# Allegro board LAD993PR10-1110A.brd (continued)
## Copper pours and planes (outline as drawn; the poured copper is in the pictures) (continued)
B++ on BOTTOM (solid shape): 50.05,30.2 50.05,29.45 49.92,29.33 49.54,29.33 49.16,28.95 49.16,28.31 48.27,27.42 48.27,24.22 47.76,23.72 47.76,19.68 47.81,19.62 47.81,19.54 48.19,19.17 48.27,19.17 48.6,18.84 49.49,18.84 49.94,18.39 49.94,16.72 50.67,15.99 52.08,15.99 52.59,16.5 53.62,16.5 53.98,16.14 55.74,16.14 56.05,16.45 56.57,16.45 56.65,16.37 56.65,15.87 57.16,15.36 57.16,13.83 57.92,13.07 58.64,13.07 58.7,13.02 58.7,10.67 58.43,10.4 58.43,8.12 58.18,7.86 55.38,7.86 52.59,10.66 49.03,10.66 48.33,11.36 48.33,15.67 46.4,17.6 46.4,18.11 44.46,20.06 44.46,20.76 44.91,20.76 44.91,21.46 44.46,21.46 44.46,21.96 44.91,21.96 44.91,22.66 44.46,22.66 44.46,29.07 45.67,30.28 49.97,30.28
B+_AMP on BOTTOM (solid shape): 267.9,21.39 267.9,21.05 268.03,20.92 269.27,20.92 269.34,20.85 269.34,19.99 269.31,19.95 267.45,19.95 267.05,20.35 267.05,21.38 267.27,21.6 267.7,21.6
B+_AMP on BOTTOM (solid shape): 262.57,31.03 263.23,31.03 263.27,31.07 263.69,31.07 263.87,30.89 263.87,30.39 263.31,29.84 262.81,29.84 262.74,29.77 262.73,29.77 262.65,29.71 262.58,29.62 262.58,29.61 262.25,29.29 258.05,29.29 257.88,29.46 257.88,31.16 258.45,31.74 261.86,31.74
B+_AMP on IN2 (solid shape): outline of 751 points within 258.35,19.95 269.68,31.87
B+_CAM on BOTTOM (solid shape): 211.52,61.14 211.52,58.04 211.21,57.74 210.04,57.74 209.64,58.13 209.22,58.13 208.9,58.45 208.9,60.98 209.28,61.36 211.3,61.36
B+_CAM on BOTTOM (solid shape): 228.51,45.68 228.51,45.39 228.6,45.3 228.87,45.3 228.97,45.2 228.97,44.92 228.89,44.75 228.91,44.57 228.39,44.04 228.39,42.9 228.28,42.78 227.57,42.78 227.47,42.89 227.47,44.11 227.47,44.41 227.47,44.42 227.49,44.54 227.47,44.67 227.47,44.68 227.47,45.04 227.47,45.05 227.49,45.18 227.47,45.3 227.47,45.31 227.47,45.68 227.57,45.79 228.41,45.79
B+_CAM on IN4 (solid shape): 211.54,58 211.54,57.52 211.06,57.04 209.97,57.04 209.84,57.17 209.84,57.83 209.74,57.93 209.74,58.31 209.89,58.46 211.08,58.46
B+_CAM on IN4 (solid shape): 228.6,46.26 229,46.26 229.19,46.07 229.19,45.18 228.84,44.82 228.84,44.72 228.56,44.44 228.03,44.44 227.75,44.72 227.75,46.17 227.85,46.27 228.58,46.27
BATDRV_CHG on TOP (solid shape): 40.01,16.5 40.01,15.87 40.14,15.74 40.52,15.74 40.65,15.61 40.65,15.23 40.52,15.1 39.51,15.1 39.25,15.36 39.25,16.5 39.35,16.6 39.92,16.6
BATDRV_CHG on BOTTOM (solid shape): 34.66,37.58 34.66,37.33 34.55,37.23 31.53,37.23 31.46,37.3 31.46,37.38 31.53,37.46 32.83,37.46 33.06,37.68 34.55,37.68
BATDRV_CHG on IN1 (solid shape): 34.74,37.65 34.74,37.26 34.65,37.17 34.61,37.15 34.57,37.14 33.98,37.14 33.6,36.76 33.6,36.31 32.97,36.31 32.97,37.14 33.6,37.77 34.62,37.77
BATSRC_CHG on TOP (solid shape): 39,16.5 39,15.36 38.74,15.1 37.73,15.1 37.6,15.23 37.6,15.61 37.73,15.74 38.11,15.74 38.24,15.87 38.24,16.5 38.34,16.6 38.9,16.6
BATSRC_CHG on BOTTOM (solid shape): 34.27,38.5 34.27,38.17 34.2,38.09 33.13,38.09 32.67,37.63 31.53,37.63 31.46,37.71 31.46,37.79 31.53,37.86 32.57,37.86 33.28,38.57 34.2,38.57
BATT++ on BOTTOM (solid shape): 47.19,16.52 47.19,11.12 46.05,9.97 46.05,9.17 45.87,8.99 41.79,8.99 41.41,9.38 41.41,13.58 41.6,13.77 43.76,13.77 44.46,14.47 44.46,16.5 44.84,16.88 46.83,16.88
BST1_5V on BOTTOM (solid shape): 52.14,26.34 52.14,25.75 52.11,25.71 51.9,25.71 51.83,25.72 51.75,25.71 50.27,25.71 50.16,25.82 50.16,26.47 50.22,26.53 51.95,26.53
BST1_NVVDD on BOTTOM (solid shape): 173.95,57.65 174.63,56.96 174.79,56.96 174.88,56.87 174.88,56.33 174.91,56.3 174.91,56.05 174.66,56.05 173.06,57.65 173.06,58.28 173.95,58.28
BST1_NVVDDS on TOP (solid shape): 202.8,56.3 202.8,55.15 203.41,54.55 204.01,53.95 204.12,53.84 204.12,53.71 204.07,53.66 203.13,53.66 201.86,54.92 201.86,56.33 201.89,56.35 202.75,56.35
BST2_NVVDD on BOTTOM (solid shape): 174.91,53.79 174.91,53.53 174.89,53.45 174.88,53.38 174.88,52.97 174.86,52.95 174.66,52.95 173.92,52.21 173.92,51.63 173.9,51.6 173.03,51.6 173.03,52.29 173.34,52.59 173.36,52.59 174.61,53.84 174.86,53.84
BST_1VALWP on BOTTOM (solid shape): 249.12,18.68 249.12,18.21 249.69,17.64 249.69,16.78 249.61,16.7 249.49,16.7 249.41,16.78 249.41,17.29 248.49,18.21 248.49,18.67 248.54,18.72 249.08,18.72
BST_1VALWP_R on BOTTOM (solid shape): 249.13,19.62 249.13,19.15 249.09,19.1 248.49,19.1 248.1,18.72 247.72,18.72 247.66,18.79 247.66,19.23 248.1,19.68 249.08,19.68
BST_3V on BOTTOM (solid shape): 51.98,20.39 51.98,19.33 52.03,19.28 52.03,18.03 51.9,17.9 50.99,17.9 50.96,17.92 50.96,18.51 51.77,19.31 51.77,20.4 51.82,20.46 51.92,20.46
BST_+0.95VSP on TOP (solid shape): 69.4,70.68 69.4,70.02 69.35,69.97 68.72,69.97 68.53,69.78 68.53,68.67 68.45,68.59 68.31,68.59 68.25,68.66 68.25,70.07 68.33,70.15 68.39,70.25 68.39,70.26 68.63,70.49 68.64,70.5 68.75,70.56 68.83,70.66 68.9,70.73 69.35,70.73
BST_+0.95VSP_R on TOP (solid shape): 71.18,70.64 71.18,70.05 71.12,69.99 69.85,69.99 69.79,70.05 69.79,70.55 69.97,70.73 71.09,70.73
BST_+1.0VSP on BOTTOM (solid shape): 222.13,46.9 222.13,46.22 222.39,45.96 222.39,44.83 222.31,44.76 222.21,44.76 221.69,45.27 221.69,45.9 221.37,46.22 221.37,46.9 221.44,46.96 222.07,46.96
BST_+1.0VSP_R on BOTTOM (solid shape): 222.07,47.81 222.07,47.33 222.03,47.29 221.45,47.29 221.4,47.35 221.4,47.55 221.26,47.68 220.67,47.68 220.62,47.74 220.62,48.09 220.67,48.14 221.74,48.14
BST_+1.8VSP on BOTTOM (solid shape): 206.25,121.54 206.25,119.57 206.18,119.5 206.05,119.5 205.99,119.56 205.99,120.22 205.61,120.6 205.61,121.53 205.66,121.58 206.2,121.58
BST_+1.8VSP_R on BOTTOM (solid shape): 206.23,121.94 205.62,121.94 205.37,121.68 205.37,121.55 205.04,121.55 205.01,121.58 205.01,122.33 205.18,122.49 206.23,122.49
BST_+1.35VS_VGAP on BOTTOM (solid shape): 143.55,116.14 143.55,115.46 142.17,114.09 141.74,114.09 141.67,114.16 141.67,114.85 141.74,114.93 142,114.93 142.55,115.48 142.55,116.09 142.66,116.2 143.49,116.2
BTST_CHG on BOTTOM (solid shape): 29.98,35.68 29.98,33.62 30.31,33.29 30.31,32.63 30.29,32.6 29.42,32.6 29.4,32.63 29.4,33.26 29.47,33.34 29.5,33.34 29.7,33.54 29.7,33.57 29.75,33.62 29.75,35.68 29.82,35.74 29.92,35.74
CHG_B+ on TOP (solid shape): 19.31,27.68 19.31,25.14 20.02,24.43 20.02,23.92 19.46,23.92 19.46,23.38 19.49,23.36 19.99,23.36 20.02,23.33 20.02,23.1 19.46,23.1 19.46,22.57 19.49,22.55 19.99,22.55 20.02,22.52 20.02,22.19 19.95,22.12 19.95,18.79 19.41,18.25 17.44,18.25 17.15,18.53 17.15,24.16 17.34,24.35 17.34,26.36 17.34,26.36 17.34,26.72 17.43,26.81 17.72,26.99 17.73,27.32 17.73,27.65 17.74,27.68 17.75,27.72 17.84,27.8 19.19,27.8
CHG_B+ on BOTTOM (solid shape): 19.31,26.53 19.31,24.12 20.46,22.98 23.5,22.98 23.76,22.72 23.76,18.66 23.5,18.41 18.55,18.41 17.28,19.68 17.28,25.52 18.42,26.66 19.19,26.66
CMSRC_CHG on BOTTOM (solid shape): 25.91,37.55 25.96,37.55 26.38,37.12 26.98,37.12 27.06,37.05 28.23,37.05 28.28,37 28.28,36.87 28.23,36.82 27.09,36.82 26.88,36.61 25.31,36.61 25.27,36.65 25.27,37.47 25.36,37.56 25.91,37.56
DH1_NVVDD on BOTTOM (solid shape): 169.78,56.15 169.78,55.51 169.4,55.13 168.26,55.13 168.11,55.29 168.11,55.79 168.67,56.35 169.58,56.35
DH1_NVVDD on BOTTOM (solid shape): 155.31,51.55 155.31,50.74 155.19,50.62 154.06,50.62 153.95,50.74 153.95,51.49 154.43,51.97 154.89,51.97
DH1_NVVDD on IN4 (solid shape): 169.78,56.17 169.78,55.9 169.02,55.13 168.26,55.13 168.11,55.29 168.11,55.79 168.67,56.35 169.61,56.35
DH1_NVVDD on IN4 (solid shape): 155.28,51.58 155.28,50.74 155.17,50.62 154.02,50.62 153.93,50.71 153.93,51.48 154.42,51.96 154.9,51.96
DH1_NVVDD on IN4 (solid shape): 175.19,57.57 175.19,57.22 174.84,56.86 173.64,56.86 173.59,56.91 173.59,57.37 173.72,57.5 173.92,57.5 174.43,58 174.76,58
DH1_NVVDDS on TOP (solid shape): 203.01,53.48 204.07,53.48 204.12,53.43 204.12,53.3 204.07,53.25 202.32,53.25 201.84,53.73 201.84,54.12 201.94,54.22 202.27,54.22
DH1_NVVDDS on BOTTOM (solid shape): 206.28,63.11 206.28,62.4 206.05,62.17 205.19,62.17 205.06,62.3 205.06,63.2 205.44,63.58 205.81,63.58
DH1_NVVDDS on BOTTOM (solid shape): 200.84,63.9 200.84,62.96 200.69,62.8 199.5,62.8 199.29,63.01 199.29,63.36 199.47,63.54 199.7,63.54 200.16,64 200.74,64
DH1_NVVDDS on IN4 (solid shape): 202.91,53.56 202.91,53.15 202.78,53.03 202.37,53.03 201.34,54.05 201.34,54.4 201.51,54.57 201.9,54.57
DH1_NVVDDS on IN4 (solid shape): 206.28,62.53 206.28,62.39 205.98,62.09 204.86,62.09 204.76,62.19 204.76,62.68 204.84,62.75 205.19,62.75 205.19,62.76 206.05,62.76
DH1_NVVDDS on IN4 (solid shape): 200.75,63.72 200.75,62.23 200.39,61.86 200.11,61.86 200.09,61.89 199.95,61.89 199.82,62.01 199.82,63.78 199.96,63.92 200.54,63.92
DH2_NVVDD on BOTTOM (solid shape): 152.04,56.21 152.04,55.6 151.95,55.51 150.12,55.51 149.95,55.69 149.95,56.08 150.2,56.33 151.92,56.33
DH2_NVVDD on BOTTOM (solid shape): 150.99,50.99 150.99,50.26 150.72,49.99 150.72,49.55 150.56,49.39 150.09,49.39 149.85,49.63 149.85,50.05 149.67,50.23 149.67,51.02 149.77,51.12 150.86,51.12
DH2_NVVDD on BOTTOM (solid shape): 175.35,53.76 175.35,52.51 175.2,52.36 175.2,52.34 174.99,52.14 174.99,51.86 174.66,51.53 174.43,51.53 174.3,51.65 174.3,52.19 174.69,52.57 174.91,52.57 175.12,52.77 175.12,53.76 175.18,53.83 175.28,53.83
DH2_NVVDD on IN1 (solid shape): 151.24,51.02 151.24,50.71 151.01,50.49 149.72,50.49 149.52,50.69 149.52,51.1 149.62,51.21 151.06,51.21
DH2_NVVDD on IN1 (solid shape): 175.27,52.64 175.27,52.42 174.99,52.14 174.99,51.65 174.71,51.37 174.33,51.37 174.24,51.46 174.24,51.82 174.3,51.88 174.3,52.19 174.89,52.77 175.14,52.77
DH_CHG on BOTTOM (solid shape): 25.98,19.02 25.98,17.96 25.79,17.77 24.77,17.77 24.48,18.07 24.48,19.03 24.68,19.23 25.77,19.23
DH_CHG on BOTTOM (solid shape): 29.58,35.7 29.58,33.59 29.45,33.47 29.25,33.47 29.12,33.59 29.12,34.38 29.37,34.64 29.37,35.7 29.41,35.74 29.54,35.74
DH_CHG on IN1 (solid shape): 29.66,34.47 29.66,32.18 29.03,32.18 29.03,34.47 29.16,34.6 29.54,34.6
DL1_NVVDD on BOTTOM (solid shape): 163.27,56.36 163.27,55.43 162.95,55.11 162.57,55.11 162.19,55.49 162.19,56.38 162.32,56.51 163.13,56.51
DL1_NVVDD on BOTTOM (solid shape): 160.79,51.81 160.79,50.85 160.63,50.69 159.67,50.69 159.57,50.79 159.57,51.19 159.85,51.47 159.85,51.78 160.07,52 160.6,52
DL1_NVVDD on BOTTOM (solid shape): 173.4,55.84 173.4,55.73 173.69,55.44 174.46,55.44 174.53,55.36 174.53,55.26 174.51,55.24 173.47,55.24 173.14,55.57 172.76,55.57 172.32,56 172.32,56.28 172.53,56.48 172.76,56.48
DL1_NVVDD on IN1 (solid shape): 163.41,56.35 163.41,55.84 163.18,55.62 162.34,55.62 162.11,55.84 162.11,56.25 162.29,56.43 163.33,56.43
DL1_NVVDD on IN1 (solid shape): 173.42,55.92 173.42,55.54 173.23,55.35 172.86,55.35 171.96,56.25 171.96,56.5 172.24,56.78 172.56,56.78
DL1_NVVDDS on TOP (solid shape): 204.89,56.17 204.89,54.09 204.86,54.07 204.73,54.07 204.68,54.12 204.68,54.92 204.35,55.26 204.35,56.15 204.5,56.3 204.75,56.3
DL1_NVVDDS on BOTTOM (solid shape): 200.64,69.48 200.64,68.67 200.47,68.5 199.5,68.5 199.31,68.69 199.31,69.48 199.54,69.71 200.42,69.71
DL1_NVVDDS on BOTTOM (solid shape): 206.08,69.71 206.08,68.77 205.88,68.57 205.09,68.57 204.86,68.8 204.86,69.74 205.01,69.89 205.9,69.89
DL1_NVVDDS on IN1 (solid shape): 204.96,56.84 204.96,55.26 204.84,55.13 204.51,55.13 204.33,55.31 204.33,56.81 204.38,56.86 204.94,56.86
DL1_NVVDDS on IN1 (solid shape): 206,69.69 206,68.6 205.85,68.44 204.9,68.44 204.82,68.52 204.82,69.75 204.96,69.89 205.8,69.89
DL1_NVVDDS on IN1 (solid shape): 201.1,69.08 201.71,69.08 201.79,69 201.79,68.49 201.74,68.44 200.34,68.44 200.06,68.72 200.06,69.46 200.21,69.61 200.57,69.61
DL2_NVVDD on BOTTOM (solid shape): 173.29,54.19 173.29,53.94 172.6,53.25 172.35,53.25 172.2,53.41 172.2,53.71 172.83,54.35 173.14,54.35
DL2_NVVDD on BOTTOM (solid shape): 145.12,57.01 145.12,56.23 144.94,56.05 144.94,55.68 144.77,55.51 144.49,55.51 143.98,56.02 143.98,56.79 144.36,57.17 144.97,57.17
DL2_NVVDD on BOTTOM (solid shape): 145.22,51.45 145.22,51.15 145.05,50.97 145.05,49.62 144.85,49.42 144.47,49.42 144.31,49.58 144.31,50.23 144.08,50.46 144.08,50.84 144.82,51.58 145.09,51.58
DL2_NVVDD on IN3 (solid shape): 173.29,54.24 173.29,54.02 172.5,53.23 172.25,53.23 172.12,53.36 172.12,53.79 172.68,54.35 173.19,54.35
DL2_NVVDD on IN3 (solid shape): 144.99,52.04 145.49,51.54 145.49,50.62 145.41,50.55 144.54,50.55 144.41,50.68 144.41,52.02 144.54,52.15 144.99,52.15
DL2_NVVDD on IN3 (solid shape): 145.12,57.06 145.12,55.59 144.99,55.46 144.92,55.46 144.87,55.51 144.56,55.51 144.03,56.05 144.03,56.84 144.36,57.17 145.02,57.17
DL_CHG on BOTTOM (solid shape): 30.77,35.68 30.77,34.84 31.48,34.13 31.48,33.8 31.35,33.67 31.15,33.67 30.57,34.25 30.57,35.68 30.63,35.74 30.71,35.74
DL_CHG on BOTTOM (solid shape): 23,27.68 23,27.42 22.87,27.3 22.87,26.79 22.74,26.66 22.41,26.66 21.8,27.27 21.8,27.69 21.91,27.8 22.87,27.8
DL_CHG on IN4 (solid shape): 31.58,34.15 31.58,33.52 30.74,32.68 30.36,32.68 30.36,33.21 30.92,33.77 30.92,33.9 30.54,34.28 30.54,34.53 30.74,34.74 31,34.74
EDPVDD on TOP (solid shape): 66.9,41.93 67.14,41.93 68.82,40.25 68.82,39.36 68.59,39.13 67.34,39.13 67.21,39.26 67.21,39.81 66.13,40.88 65.29,40.88 65.28,40.9 65.28,41.17 65.81,41.17 65.81,41.61 65.28,41.61 65.28,41.92 65.39,42.03 66.8,42.03
GVDD on BOTTOM (solid shape): 261.22,23.23 261.22,22.95 261.58,22.6 262.09,22.6 262.3,22.39 262.3,22.08 262.21,21.99 261.3,21.99 260.69,22.6 260.69,23.28 260.72,23.31 261.15,23.31
IFP_IOVDDA on TOP (solid shape): 160.16,83.2 160.16,82.63 160.22,82.57 160.22,82.11 159.97,81.85 159.13,81.85 159.03,81.96 159.03,83.28 159.15,83.4 159.95,83.4
IFP_IOVDDB on TOP (solid shape): 163.02,84.63 163.02,83.82 163.48,83.35 163.64,83.35 163.77,83.23 163.77,83.01 163.68,82.91 163.15,82.91 162.98,82.74 162.44,82.74 162.39,82.79 162.39,84.57 162.47,84.65 162.47,84.65 162.51,84.68 162.97,84.68
LDO_1VALWP on BOTTOM (solid shape): 249.36,15.2 249.36,14.65 249.26,14.54 249.26,13.96 248.29,12.99 248.29,12.56 248.22,12.49 247.63,12.49 247.53,12.59 247.53,13.33 248.45,14.24 248.45,15.21 248.52,15.29 249.28,15.29
LDO_+0.95VSP on TOP (solid shape): 70.88,67.05 70.88,66.54 70.8,66.46 68.67,66.46 68.59,66.54 68.59,67.1 68.67,67.17 70.75,67.17
LDO_+1.0VSP on BOTTOM (solid shape): 222.05,43.25 222.05,42.71 221.94,42.6 221.34,42.6 221.14,42.4 221.14,41.92 221,41.78 220.73,41.78 220.32,42.2 220.32,42.22 220.02,42.52 220.02,42.52 220.02,43.2 220.14,43.33 221.98,43.33
LDO_+1.8VSP on BOTTOM (solid shape): 205.93,118.02 205.93,117.44 205.11,116.63 203.69,116.63 203.59,116.73 203.59,117.19 203.74,117.34 204.43,117.34 204.66,117.57 204.66,117.8 204.91,118.05 205.62,118.05 205.67,118.1 205.85,118.1
LG_3V on BOTTOM (solid shape): 51.17,20.8 51.17,20.51 50.35,19.7 50.35,19.65 50.12,19.42 49.92,19.42 49.79,19.55 49.79,20.39 50.22,20.81 50.37,20.81 50.43,20.87 51.1,20.87
LG_3V on BOTTOM (solid shape): 61.73,10.72 61.73,10.02 61.07,9.36 61.07,8.98 60.97,8.88 59.32,8.88 59.06,9.13 59.06,9.52 59.19,9.64 60.46,9.64 60.84,10.02 60.84,10.79 60.97,10.91 61.54,10.91
LG_5V on TOP (solid shape): 50.3,37.07 50.3,35.3 50.17,35.17 49.54,35.17 49.41,35.3 49.41,37.07 49.54,37.2 50.17,37.2
LG_5V on TOP (solid shape): 50.21,23.18 50.21,22.59 50.09,22.47 49.19,22.47 49.06,22.6 49.06,23.38 49.16,23.49 49.91,23.49
LG_5V on BOTTOM (solid shape): 50.1,36.92 50.1,36.75 50.3,36.56 50.3,34.02 50.17,33.9 49.71,33.9 49.54,34.06 49.54,35.24 49.54,35.24 49.54,37 49.67,37.14 49.89,37.14
LG_5V on BOTTOM (solid shape): 50.66,22.47 51.11,22.47 51.18,22.4 51.18,22.31 51.12,22.25 50.93,22.25 50.87,22.31 50.05,22.31 49.95,22.41 49.26,22.41 49.12,22.55 49.12,22.84 49.25,22.98 50.15,22.98
LG_+1.35VS_VGAP on BOTTOM (solid shape): 139.94,114.82 139.94,114.16 139.86,114.09 139.02,114.09 138.95,114.16 138.95,114.93 139.13,115.1 139.66,115.1
LG_+1.35VS_VGAP on BOTTOM (solid shape): 144.28,130.9 144.28,129.89 143.57,129.18 143.11,129.18 142.96,129.32 142.96,130.01 143.93,130.98 144.21,130.98
LG_+1.35VS_VGAP on IN1 (solid shape): 139.91,115.38 139.91,114.24 139.74,114.06 139,114.06 138.9,114.16 138.9,115.33 139.15,115.59 139.71,115.59
LG_+1.35VS_VGAP on IN1 (solid shape): 144.28,130.9 144.28,129.89 143.47,129.07 143.06,129.07 142.96,129.17 142.96,130.01 143.93,130.98 144.21,130.98
LINE1-L_C on TOP (solid shape): 296.73,14.41 296.73,13.81 296.7,13.78 295.02,13.78 294.93,13.86 294.93,14.42 295.04,14.53 296.61,14.53
LINE1-L_R on TOP (solid shape): 293.51,14.6 294.52,14.6 294.65,14.47 294.65,13.89 294.57,13.81 292.56,13.81 292.24,14.13 292.24,14.67 292.31,14.75 293.35,14.75
LINE1_R on TOP (solid shape): 294.61,16.27 294.61,15.28 294.56,15.23 293.76,15.23 293.7,15.28 293.7,16.41 293.81,16.52 294.36,16.52
LX1_NVVDD on TOP (solid shape): 167.01,61.66 167.01,52.44 166.13,51.55 163.6,51.55 163.46,51.69 163.46,56.12 164.35,57.01 164.35,58.16 163.59,58.92 160.77,58.92 160.59,58.74 160.59,58.58 160.02,58.58 159.93,58.59 159.8,58.58 159.69,58.49 159.61,58.39 159.6,58.26 159.61,58.13 159.69,58.02 159.8,57.94 159.93,57.93 160.02,57.94 160.59,57.94 160.59,57.65 159.52,56.58 159.52,51.68 159.39,51.55 156.35,51.55 155.84,52.06 155.84,56.12 156.96,57.25 156.96,59.29 157.62,59.95 157.62,61.51 158.4,62.3 166.38,62.3
LX1_NVVDD on BOTTOM (solid shape): 172.68,57.62 174.46,55.84 174.47,55.84 174.53,55.78 174.53,55.69 174.47,55.63 173.7,55.63 173.64,55.68 173.64,56.02 172.35,57.32 171.79,57.32 171.79,58.28 172.68,58.28
LX1_NVVDD on BOTTOM (solid shape): 168.26,62.71 168.26,57.5 166.9,56.14 166.39,56.14 166.15,55.9 166.15,51.7 166.18,51.68 166.05,51.55 163.56,51.55 163.46,51.65 163.46,56.46 163.21,56.71 160.03,56.71 159.64,56.32 159.64,51.56 159.61,51.53 156.97,51.53 156.92,51.58 156.92,57 158.4,58.49 158.4,62.4 159.15,63.14 167.83,63.14
LX1_NVVDDS on TOP (solid shape): 192.16,70.48 192.16,68.82 192.8,68.19 205.62,68.19 205.67,68.14 205.67,65.34 205.47,65.14 195.56,65.14 193.56,63.13 189.85,63.13 189.37,63.62 189.37,70.6 189.62,70.86 191.78,70.86
LX1_NVVDDS on TOP (solid shape): 204.19,56.23 204.19,55.24 204.2,55.21 204.51,54.9 204.51,54.12 204.45,54.07 204.33,54.07 204.25,54.14 204.25,54.17 203.13,55.29 203.13,56.33 203.15,56.35 204.07,56.35
LX1_NVVDDS on BOTTOM (solid shape): 194.45,70.35 194.45,68.7 194.94,68.2 205.66,68.2 205.75,68.11 205.75,65.39 205.51,65.14 195.08,65.14 193.18,63.24 190.27,63.24 189.41,64.1 189.41,71.15 189.87,71.62 193.18,71.62
LX1_NVVDDS on IN1 (solid shape): 204.12,55.03 204.12,54.78 204.02,54.68 203.59,54.68 202.45,55.82 202.45,56.05 202.55,56.15 203.01,56.15
LX1_NVVDDS on IN3 (solid shape): 194.45,70.98 194.45,68.7 194.95,68.19 205.57,68.19 205.67,68.09 205.67,65.31 205.5,65.14 195.08,65.14 193.32,63.38 193.27,63.38 192.87,62.98 190.71,62.98 189.37,64.33 189.37,70.7 189.9,71.24 194.19,71.24
LX1_NVVDDS on IN4 (solid shape): 194.45,70.98 194.45,68.7 194.95,68.19 205.57,68.19 205.75,68.01 205.75,65.45 205.5,65.19 195.06,65.19 192.85,62.98 190.03,62.98 189.39,63.62 189.39,70.73 189.9,71.24 194.19,71.24
LX2_NVVDD on TOP (solid shape): 157.21,61.86 157.21,60.11 156.7,59.6 155.41,59.6 155.25,59.45 155.25,57.19 149.31,57.19 148.27,56.15 148.27,46.35 148.14,46.22 145.53,46.22 145.35,46.4 145.35,59.52 145.55,59.72 145.55,61.41 146.52,62.37 156.7,62.37
LX2_NVVDD on BOTTOM (solid shape): 174.51,54.19 174.51,54.04 174.48,54.01 174.35,54.01 172.65,52.31 172.68,52.29 172.68,51.65 172.65,51.63 171.82,51.63 171.79,51.65 171.79,52.29 171.94,52.29 173.57,53.91 173.57,54.09 173.65,54.17 174.24,54.17 174.29,54.23 174.47,54.23
LX2_NVVDD on BOTTOM (solid shape): 157.2,62.83 157.21,62.83 157.21,60.11 156.7,59.6 155.41,59.6 155.25,59.45 155.25,57.72 154.72,57.19 149.31,57.19 148.27,56.15 148.27,46.08 148.04,45.85 145.37,45.85 145.35,45.87 145.35,62.16 146.4,63.22 156.81,63.22
LX2_NVVDD on IN1 (solid shape): 157.21,62.84 157.21,60.11 156.7,59.6 155.41,59.6 155.25,59.45 155.25,57.44 155,57.19 149.31,57.19 148.27,56.15 148.27,46.35 148.14,46.22 145.45,46.22 145.35,46.32 145.35,62.2 146.36,63.21 156.85,63.21
LX2_NVVDD on IN3 (solid shape): 173.62,53.53 173.62,52.87 173.29,52.54 173.29,52.14 172.96,51.81 172.65,51.81 172.65,53.03 173.24,53.61 173.54,53.61
LX2_NVVDD on IN3 (solid shape): 148.85,49.83 148.85,49.39 148.82,49.36 148.36,49.36 148.24,49.24 148.24,46.37 148.07,46.19 145.51,46.19 145.35,46.35 145.35,50.35 148.34,50.35
LX2_NVVDD on IN3 (solid shape): 150.31,61.64 150.31,58.17 149.39,57.24 149.36,57.24 148.24,56.12 148.27,56.1 148.27,52.24 148.04,52.01 145.48,52.01 145.35,52.14 145.35,60.19 147.19,62.02 149.92,62.02
LX2_NVVDD on IN4 (solid shape): 157.21,62.7 157.21,60.11 156.7,59.6 155.43,59.6 155.28,59.45 155.28,57.32 155.15,57.19 149.29,57.19 148.27,56.17 148.27,48.59 146.15,46.47 145.35,46.47 145.35,62.67 145.85,63.17 156.74,63.17
LX_1VALWP on TOP (solid shape): 253.25,17.47 253.25,17.34 252.46,16.55 252.46,14.49 252.61,14.34 252.61,12.82 252.36,12.56 251.47,12.56 251.09,12.94 251.09,16.25 250.71,16.63 247.91,16.63 247.79,16.75 247.79,17.64 248.12,17.97 252.74,17.97
LX_1VALWP on BOTTOM (solid shape): 253.26,17.5 253.26,17.15 252.49,16.38 251.61,16.38 251.55,16.45 251.55,16.55 251.88,16.88 251.98,16.88 252.61,17.52 252.62,17.52 252.73,17.63 253.14,17.63
LX_1VALWP on BOTTOM (solid shape): 247.53,18.6 248.1,18.6 248.17,18.53 248.17,18.02 249.18,17.01 249.18,16.73 249.36,16.55 249.36,16.02 249.29,15.94 248.37,15.94 248.12,15.69 248.12,14.42 247.28,13.58 247.28,11.93 247.14,11.79 243.68,11.79 243.44,12.03 243.44,17.47 243.46,17.48 243.46,17.81 244.31,18.66 247.47,18.66
LX_3V on BOTTOM (solid shape): 70.62,14.47 70.62,10.28 70.37,10.02 65.49,10.02 64.14,11.37 59.4,11.37 59.26,11.51 59.26,13.77 60.33,14.85 70.24,14.85
LX_3V on BOTTOM (solid shape): 52.39,20.4 52.39,19.21 53.55,18.04 53.55,16.68 53.5,16.63 53.2,16.63 53.1,16.73 53.1,17.67 52.9,17.87 52.3,17.87 52.17,18 52.17,20.39 52.24,20.46 52.33,20.46
LX_3V on IN1 (solid shape): 53.73,17.71 53.73,16.69 54.38,16.05 54.38,15.72 53.82,15.72 53.1,16.44 53.1,17.71 53.22,17.83 53.6,17.83
LX_5V on TOP (solid shape): 47.59,32.93 47.59,31.19 47.13,30.72 45.48,30.72 45.35,30.85 45.35,31.99 46.36,33.01 47.51,33.01
LX_5V on BOTTOM (solid shape): 50.05,33.52 50.05,30.85 49.92,30.72 45.35,30.72 43.19,28.57 40.14,28.57 39.89,28.82 39.89,32.76 40.78,33.65 49.92,33.65
LX_5V on BOTTOM (solid shape): 52.21,25.26 52.21,24.5 52.46,24.25 52.46,23.62 52.38,23.54 52.38,22.7 52.33,22.65 52.22,22.65 52.16,22.71 52.16,23.88 51.44,24.6 51.44,25.26 51.57,25.39 52.08,25.39
LX_5V on IN4 (solid shape): 52.16,24.58 52.39,24.34 52.4,24.33 52.47,24.2 52.58,24.12 52.61,24.1 52.61,23.87 52.41,23.66 52.13,23.66 51.5,24.3 51.5,25.57 52.16,25.57
LX_+0.95VSP on TOP (solid shape): 71.64,69.21 71.64,68.44 71.38,68.19 71.26,68.19 71.16,68.09 70.36,68.09 70.36,68.09 70.21,68.09 69.93,67.81 68.67,67.81 68.59,67.89 68.59,68.44 68.82,68.67 68.82,69.69 68.97,69.84 71,69.84
LX_+0.95VSP on BOTTOM (solid shape): 72.02,73.14 72.02,68.7 71.13,67.81 68.34,67.81 67.95,68.19 66.05,68.19 65.8,68.44 65.8,69.21 66.56,69.97 68.03,69.97 69.99,71.93 69.99,73.14 70.11,73.27 71.89,73.27
LX_+1.0VSP on TOP (solid shape): 225.31,45.71 225.31,44.87 225.09,44.66 221.17,44.66 220.99,44.83 220.99,45.75 221.13,45.9 221.37,45.9 221.65,45.62 222.18,45.62 222.48,45.92 225.1,45.92
LX_+1.0VSP on BOTTOM (solid shape): 225.43,45.89 225.43,44.77 225.1,44.44 224.34,44.44 224.27,44.52 224.27,44.59 224.34,44.67 224.62,44.67 224.75,44.8 224.75,45.89 224.88,46.01 225.31,46.01
LX_+1.0VSP on BOTTOM (solid shape): 220.55,47.5 220.7,47.43 220.86,47.4 221.12,47.4 221.12,46.22 221.5,45.84 221.5,45.16 222.06,44.6 222.06,44.05 221.98,43.98 217.01,43.98 216.8,44.19 216.8,47.36 216.95,47.51 220.54,47.51
LX_+1.8VSP on TOP (solid shape): 205.58,120.28 206.11,120.28 206.47,120.64 208.85,120.64 209.03,120.46 209.03,119.57 208.85,119.4 205.1,119.4 204.84,119.66 204.84,120.51 204.96,120.64 205.22,120.64
LX_+1.8VSP on BOTTOM (solid shape): 209.05,119.19 209.03,119.17 208.16,119.17 208.11,119.22 208.11,119.34 208.14,119.37 208.16,119.37 208.29,119.5 208.29,120.34 208.47,120.51 209.05,120.51
LX_+1.8VSP on BOTTOM (solid shape): 204.58,122.6 204.58,121.4 204.59,121.38 205.37,121.38 205.37,120.56 205.84,120.09 205.84,119.45 205.9,119.39 205.9,118.79 205.85,118.74 205.64,118.74 205.62,118.76 204.81,118.76 204.2,119.37 201.91,119.37 201.86,119.42 201.86,123.28 201.94,123.36 203.82,123.36
LX_CHG on TOP (solid shape): 25.79,23.99 25.79,22.6 25.66,22.47 24.14,22.47 24.01,22.6 24.01,23.99 24.27,24.25 25.54,24.25
LX_CHG on BOTTOM (solid shape): 31.12,24.76 31.12,19.17 30.74,18.79 26.93,18.79 25.92,19.8 24.39,19.8 24.14,20.06 24.14,22.85 23.27,23.72 23.27,27.27 23.55,27.55 28.33,27.55
LX_CHG on BOTTOM (solid shape): 29.17,35.7 29.17,34.66 28.99,34.48 28.99,32.68 28.94,32.63 28.23,32.63 28.15,32.71 28.15,34.23 28.56,34.64 28.76,34.64 28.97,34.84 28.97,35.7 29,35.74 29.13,35.74
LX_CHG on IN1 (solid shape): 28.78,34.47 28.78,32.69 28.39,32.31 28.08,32.31 28.08,32.88 28.14,32.95 28.14,34.47 28.27,34.6 28.65,34.6
LX_DDR on BOTTOM (solid shape): 106.59,12.36 106.59,9.41 107.2,8.8 107.2,7.33 106.97,7.1 105.5,7.1 105.04,7.56 105.04,8.6 104.96,8.68 104.96,8.74 103.32,10.37 103.32,10.49 103.16,10.66 102.42,10.66 101.31,10.66 101.1,10.86 101.1,12.33 103.03,12.33 103.49,12.79 106.16,12.79
PQ703_S on TOP (solid shape): 38.49,20.44 38.49,19.29 39,18.79 39,17.01 38.87,16.88 34.93,16.88 34.68,17.14 34.68,20.31 34.93,20.56 38.36,20.56
PQ703_S on BOTTOM (solid shape): 42.81,22.98 42.81,19.93 42.68,19.8 42.08,19.8 41.98,19.9 41.98,20.4 41.96,20.43 41.6,20.76 41.25,20.43 41.22,20.4 41.22,19.8 40.52,19.8 39.25,18.53 38.24,18.53 37.73,18.02 37.73,17.26 37.47,17.01 34.81,17.01 34.68,17.14 34.68,22.98 35.06,23.36 42.43,23.36
REGN_CHG on BOTTOM (solid shape): 30.38,35.68 30.38,34.22 31.3,33.29 31.56,33.29 31.58,33.26 31.58,32.63 31.56,32.6 31.35,32.6 30.74,31.99 30.36,31.99 30.24,32.12 30.24,32.38 30.36,32.5 30.52,32.5 30.62,32.6 30.62,33.31 30.16,33.77 30.16,35.68 30.22,35.74 30.31,35.74
RING2 on BOTTOM (solid shape): 291.47,19.93 291.47,19.25 291.73,18.99 291.73,17.9 291.36,17.9 291.36,18.21 291.35,18.23 291.05,18.53 290.74,18.53 290.73,18.55 289.87,18.55 289.57,18.85 289.57,20.31 289.7,20.44 290.97,20.44
RING2 on IN1 (solid shape): 281.34,19.1 281.34,18.33 281.16,18.15 280.63,18.15 279.74,19.04 279.74,19.88 279.89,20.03 280.41,20.03
RING2 on IN1 (solid shape): 290.59,19.47 290.59,19.12 289.62,18.15 288.78,18.15 288.15,18.79 288.15,19.68 290.38,19.68
RING2_R on BOTTOM (solid shape): 295.46,20.36 295.46,19.32 294.43,18.28 294.43,18.03 294.3,17.9 292.11,17.9 292.11,18.48 292.29,18.66 292.87,18.66 293.84,19.62 293.84,20.44 294.12,20.72 295.11,20.72
SLEEVE on BOTTOM (solid shape): 298.33,14.34 298.33,12.71 298.29,12.67 297.61,12.67 297.57,12.72 297.57,14.34 297.7,14.47 298.21,14.47
SLEEVE on BOTTOM (solid shape): 286.9,21.45 286.9,19.68 286.42,19.19 282.55,19.19 282.27,18.91 281.06,18.91 280.93,19.04 280.93,19.93 281.19,20.18 283.22,20.18 284.9,21.86 286.5,21.86
SLEEVE on IN4 (solid shape): 298.34,14.97 298.34,13.41 298.2,13.27 297.17,13.27 297.03,13.41 297.03,15.06 297.11,15.14 298.17,15.14
SLEEVE on IN4 (solid shape): 287.59,22.47 287.59,21.96 287.33,21.71 287.33,21 287.11,20.77 286.53,20.77 286.44,20.86 286.15,20.86 286.06,20.95 286.06,22.06 286.7,22.7 287.36,22.7
SLEEVE_R on BOTTOM (solid shape): 297.26,13.18 297.26,10.28 299.42,8.12 299.42,7.74 299.03,7.36 298.7,7.36 297.93,8.12 297.77,8.12 296.54,9.35 296.54,9.51 296.17,9.87 296.17,13.02 296.37,13.21 297.23,13.21
SNUB_1VALWP on TOP (solid shape): 255.15,11.47 255.08,11.39 254.3,11.39 254.18,11.52 254.18,14.38 254.21,14.42 255.15,14.42
SNUB_3V on BOTTOM (solid shape): 66.3,9.39 66.3,7.1 66.18,6.98 65.54,6.98 65.29,7.23 65.29,8.12 65.03,8.37 64.53,8.37 64.4,8.5 64.4,9.39 64.53,9.52 66.18,9.52
SNUB_5V on TOP (solid shape): 45.22,34.28 45.22,32.88 44.84,32.5 44.84,31.23 44.76,31.15 43.65,31.15 43.57,31.23 43.57,33.52 44.42,34.37 45.14,34.37
SNUB_+0.95VSP on BOTTOM (solid shape): 64.86,69.94 64.86,68.29 64.81,68.24 62.37,68.24 62.09,68.52 62.09,69.57 62.27,69.75 63.04,69.75 63.34,70.05 64.74,70.05
SNUB_+1.8VSP on TOP (solid shape): 209.71,116.8 210.17,116.35 211.03,116.35 211.03,115.74 210.98,115.69 210.17,115.69 210.12,115.74 208.77,115.74 208.65,115.86 208.65,117.39 208.75,117.49 209.71,117.49
SNUB_CHG on TOP (solid shape): 25.79,26.15 25.79,25.26 25.66,25.14 23.25,25.14 23.12,25.26 23.12,26.15 23.25,26.28 25.66,26.28
SW_+1.35VS_VGAP on TOP (solid shape): 150.01,132.24 150.01,131.22 150.43,130.8 150.43,126.61 150.25,126.43 145.58,126.43 145.27,126.13 139.58,126.13 139.41,126.3 139.41,128.77 139.46,128.82 143.52,128.82 144.54,129.83 144.54,130.7 145.07,131.23 146.19,131.23 146.57,131.61 146.57,132.32 146.82,132.58 149.67,132.58
SW_+1.35VS_VGAP on BOTTOM (solid shape): 141.13,117.19 141.13,115.86 141.02,115.76 141.02,115.2 140.95,115.13 140.95,114.19 140.88,114.11 140.7,114.11 140.68,114.14 140.68,115.17 140.54,115.31 140.54,115.68 140.52,115.7 140.52,115.77 140.19,116.09 140.19,117.36 140.22,117.39 140.93,117.39
SW_+1.35VS_VGAP on BOTTOM (solid shape): 150.39,132.49 150.43,132.43 150.43,132.21 150.39,132.04 150.43,131.88 150.43,126.61 150.25,126.43 145.58,126.43 145.23,126.09 139.47,126.09 139.41,126.15 139.41,128.77 139.46,128.82 143.52,128.82 144.54,129.83 144.54,132.27 144.84,132.58 150.3,132.58
SW_+1.35VS_VGAP on IN1 (solid shape): 141.08,116.45 141.08,115.58 141.04,115.54 141.04,115.32 140.85,115.13 140.65,115.13 140.4,115.38 140.4,116.53 140.5,116.63 140.9,116.63
SW_+1.35VS_VGAP on IN1 (solid shape): 150.33,132.49 150.33,131.69 150.45,131.56 150.45,126.63 150.25,126.43 145.63,126.43 145.6,126.46 145.58,126.46 145.25,126.13 139.52,126.13 139.38,126.27 139.38,128.67 139.51,128.79 143.52,128.79 144.54,129.81 144.54,132.3 144.82,132.58 150.24,132.58
SW_+1.35VS_VGAP on IN3 (solid shape): 150.39,132.49 150.43,132.43 150.43,132.21 150.39,132.04 150.43,131.88 150.43,126.61 150.25,126.43 145.58,126.43 145.23,126.09 139.46,126.09 139.41,126.14 139.41,126.25 139.41,126.25 139.41,128.77 139.46,128.82 143.52,128.82 144.54,129.83 144.54,132.27 144.84,132.58 150.3,132.58
SW_+1.35VS_VGAP on IN4 (solid shape): 150.39,132.49 150.43,132.43 150.43,132.21 150.39,132.04 150.43,131.88 150.43,126.61 150.25,126.43 145.58,126.43 145.27,126.13 139.53,126.13 139.41,126.25 139.41,128.77 139.46,128.82 143.52,128.82 144.54,129.83 144.54,132.27 144.84,132.58 150.3,132.58
SWF_BSNL on TOP (solid shape): 306.91,5.46 306.91,4.12 306.66,3.88 306,3.88 305.7,4.18 305.7,4.66 305.09,5.27 305.09,6.52 305.23,6.66 305.71,6.66
SWF_BSNL on BOTTOM (solid shape): 262.24,13.85 262.24,10.44 262.07,10.27 260.51,10.27 260.4,10.39 260.4,11.56 260.82,11.98 260.82,13.84 260.92,13.95 262.14,13.95
SWF_BSNL on IN2 (solid shape): 306.94,4.79 306.94,2.53 306.59,2.17 306.13,2.17 305.7,2.61 305.7,4.84 305.98,5.12 306.61,5.12
SWF_BSNL on IN2 (solid shape): 262.98,11.24 265.49,11.24 265.64,11.09 265.64,10.15 265.47,9.97 260.61,9.97 260.35,10.23 260.35,11.39 260.63,11.67 262.55,11.67
SWF_BSNR on TOP (solid shape): 304.71,6.57 304.71,5.29 305.34,4.66 305.34,3.94 305.14,3.74 304.42,3.74 304.3,3.85 304.3,4.85 304.07,5.08 304.07,6.54 304.19,6.66 304.61,6.66
SWF_BSNR on BOTTOM (solid shape): 258.88,13.62 258.88,10.31 258.83,10.27 256.9,10.27 256.85,10.32 256.85,13.43 257.36,13.94 258.55,13.94
SWF_BSNR on IN2 (solid shape): 305.42,6.31 305.42,4.31 304.96,3.85 304.33,3.85 304.17,4 304.17,6.39 304.28,6.49 305.24,6.49
SWF_BSNR on IN2 (solid shape): 260.91,12.77 260.91,12.46 259.14,10.68 257.27,10.68 257.05,10.9 257.05,11.59 257.39,11.93 258.58,11.93 260.03,13.38 260.3,13.38
UG_3V on BOTTOM (solid shape): 51.58,20.4 51.58,19.35 51.04,18.81 50.84,18.81 50.71,18.94 50.71,19.88 51.02,20.18 51.06,20.18 51.34,20.46 51.52,20.46
UG_3V on BOTTOM (solid shape): 60.34,10.99 60.34,10.36 59.88,9.9 58.91,9.9 58.71,10.1 58.71,10.45 59.4,11.14 60.19,11.14
UG_5V on TOP (solid shape): 51.42,28.87 51.42,23.08 51.19,22.85 50.81,22.85 50.63,23.03 50.63,23.51 50.33,23.82 50.33,28.87 50.42,28.97 51.32,28.97
UG_5V on BOTTOM (solid shape): 51.52,23.52 51.52,22.96 51.58,22.9 51.58,22.71 51.52,22.65 51.19,22.65 50.76,23.08 50.76,23.9 50.85,23.99 51.05,23.99
UG_5V on BOTTOM (solid shape): 51.7,28.82 51.7,27.8 51.57,27.68 50.3,27.68 49.58,28.4 49.58,28.73 49.79,28.95 51.57,28.95
UG_+1.35VS_VGAP on BOTTOM (solid shape): 144.04,123.83 144.04,122.41 143.85,122.21 143.34,122.21 142.96,122.6 142.96,123.96 143.17,124.17 143.7,124.17
UG_+1.35VS_VGAP on BOTTOM (solid shape): 142.33,115.94 142.33,115.66 141.74,115.08 141.61,115.08 141.46,114.93 141.46,114.16 141.39,114.09 141.23,114.09 141.16,114.16 141.16,115.48 141.67,115.99 142.28,115.99
UG_+1.35VS_VGAP on IN1 (solid shape): 142.4,116.5 142.4,115.56 141.79,114.95 141.46,114.95 141.34,115.08 141.34,115.46 141.77,115.89 141.77,116.37 141.92,116.53 142.38,116.53
UG_+1.35VS_VGAP on IN1 (solid shape): 144.15,123.28 144.15,122.37 143.72,121.94 143.72,121.2 143.65,121.12 143.16,121.12 143.06,121.22 143.06,122.27 143.44,122.65 143.44,123.23 143.62,123.41 144.03,123.41
VCORE_B+ on TOP (solid shape): 110.12,130.93 110.12,127.37 109.99,127.24 105.55,127.24 105.42,127.37 105.42,130.71 105.95,131.24 109.8,131.24
VCORE_B+ on TOP (solid shape): 130.18,132.2 130.18,127.5 130.06,127.37 125.1,127.37 124.85,127.63 124.85,129.73 125.02,130.04 124.85,130.34 124.85,131.31 125,131.46 128.05,131.46 128.28,131.69 128.28,132.32 128.41,132.45 129.93,132.45
VCORE_B+ on TOP (solid shape): 118.65,132.04 119.17,132.04 119.26,131.94 119.26,131.44 121.29,131.44 121.29,132.04 121.8,132.04 121.8,130.42 121.57,130.18 121.45,130.1 121.36,129.97 121.35,129.97 121.17,129.78 121.17,129.28 121.16,129.27 121.16,128.34 121.06,128.16 121.04,127.95 121.04,127.73 120.81,127.5 118.3,127.5 118.25,127.45 118.25,127.42 118.2,127.37 115.2,127.37 115.07,127.5 115.07,131.94 115.2,132.07 118.65,132.07
VCORE_B+ on BOTTOM (solid shape): 110.12,130.67 110.12,127.63 109.79,127.29 108.24,127.29 108.06,127.12 104.95,127.12 104.89,127.18 104.89,128.25 105.01,128.36 105.01,128.39 106.31,128.39 106.44,128.51 106.44,128.82 106.51,128.89 106.51,129.46 106.61,129.57 106.61,129.57 107.2,130.17 107.2,131.18 107.32,131.31 109.48,131.31
VCORE_B+ on BOTTOM (solid shape): 130.02,130.21 130.02,127.43 129.96,127.37 128.41,127.37 128.28,127.24 124.98,127.24 124.94,127.28 124.94,128.36 125.07,128.49 125.1,128.51 126.37,128.51 126.5,128.64 126.5,128.95 126.55,129.06 126.57,129.18 126.57,129.6 127.26,130.29 127.26,131.29 127.36,131.39 128.84,131.39
VCORE_B+ on BOTTOM (solid shape): 120.66,131.82 120.66,130.42 120.53,130.29 120.53,129.98 120.47,129.73 120.53,129.49 120.53,128.04 120.47,127.98 120.47,127.56 120.38,127.47 118.3,127.47 118.07,127.24 114.85,127.24 114.79,127.31 114.79,128.36 114.89,128.47 116.17,128.47 116.34,128.64 116.34,128.95 116.39,129.06 116.41,129.18 116.41,129.6 116.72,129.91 116.72,131.61 117.18,132.07 120.41,132.07
VCORE_B+ on IN1 (solid shape): outline of 845 points within 104.4,127.12 130.18,133.72
VCORE_B+ on IN4 (solid shape): outline of 243 points within 106.18,127.37 129.3,131.05
N50153 on BOTTOM (solid shape): 72.1,86.96 72.1,84.5 72.45,84.14 72.45,83.78 72.35,83.68 71.46,83.68 71.38,83.76 71.38,84.29 71.79,84.7 71.79,86.93 71.89,87.04 72.02,87.04
N13351923 on BOTTOM (solid shape): 72.45,86.96 72.45,86.02 73.37,85.11 73.8,85.11 74,84.9 74,84.09 73.85,83.94 73.09,83.94 72.22,84.8 72.22,86.93 72.32,87.04 72.37,87.04
N19473637 on TOP (solid shape): 145.15,27.65 145.15,26.41 144.99,26.25 143.8,26.25 143.66,26.39 143.66,27.68 143.8,27.82 144.98,27.82
N19473637 on BOTTOM (solid shape): 146.42,27.46 146.42,25.58 146.15,25.31 145.67,25.31 145.3,24.94 145.3,23.34 145.15,23.19 144.76,23.19 144.61,23.34 144.61,24.97 144.31,25.27 144.31,27.5 144.55,27.74 146.14,27.74
N120970730 on TOP (solid shape): 128,123.21 128.03,123.18 128.03,120.51 127.9,120.39 127.01,120.39 126.88,120.51 126.88,123.18 127.01,123.31 127.9,123.31
N120976432 on TOP (solid shape): 104.66,123.24 104.66,120.26 104.53,120.13 103.64,120.13 103.51,120.26 103.51,123.27 103.62,123.38 104.52,123.38
N120976432 on BOTTOM (solid shape): 102.8,125.86 102.8,124.65 102.95,124.5 106.64,124.5 107.58,123.56 107.58,120.13 107.2,119.75 102.12,119.75 101.74,120.13 101.74,125.72 101.99,125.97 102.69,125.97
N121795600 on TOP (solid shape): 125.29,123.04 125.29,120.49 125.16,120.36 124.27,120.36 123.89,120.74 123.89,123.04 124.12,123.28 125.06,123.28
N121795600 on BOTTOM (solid shape): 122.87,126 122.87,124.91 123.14,124.64 126.74,124.64 126.88,124.5 126.88,120.26 126.5,119.88 121.17,119.88 120.91,120.13 120.91,124.32 121.42,124.83 121.42,125.47 122.06,126.1 122.77,126.1
N122017994 on TOP (solid shape): 114.56,123.34 114.56,120.39 114.44,120.26 113.55,120.26 113.42,120.39 113.42,123.32 113.61,123.51 114.4,123.51
N122017994 on BOTTOM (solid shape): 112.7,126 112.7,124.94 113,124.64 116.66,124.64 117.36,123.94 117.36,120.13 117.19,119.96 111.68,119.96 111.26,120.39 111.26,125.49 111.86,126.09 112.61,126.09
N123983992 on TOP (solid shape): 77.48,116.58 77.48,110.99 77.23,110.73 75.96,110.73 75.7,110.99 75.7,115.94 76.46,116.7 77.35,116.7
N123983992 on BOTTOM (solid shape): 80.4,118.74 80.4,117.24 80.39,117.24 80.39,116.68 80.4,116.68 80.4,113.09 80.1,112.79 77.65,111.64 76.49,109.18 76.48,108.76 76.5,108.33 76.52,108.18 76.55,108.04 76.45,107.94 74.05,107.94 73.21,108.78 73.21,109.92 73.3,110.01 74.47,110.01 74.67,110.21 74.67,113.89 74.94,114.16 74.94,114.8 76.97,116.83 76.97,118.74 77.35,119.12 80.02,119.12
N123984041 on TOP (solid shape): 134.95,131.32 135.65,131.32 135.65,131.84 136.15,131.84 136.15,131.32 136.85,131.32 136.85,131.84 138.11,131.84 138.44,131.51 138.44,129.56 139.28,128.72 139.28,125.92 139.02,125.67 134.96,125.67 134.2,126.43 134.2,127.15 134.6,127.55 134.6,127.92 134.63,128 134.64,128.07 135.21,128.47 134.53,128.36 134.29,128.45 134.05,128.36 133.98,128.33 133.92,128.36 133.83,128.41 133.72,128.44 133.69,128.44 133.61,128.44 133.61,128.72 133.54,128.8 133.54,131.36 134.02,131.84 134.95,131.84
N123984041 on BOTTOM (solid shape): 138.44,130.67 138.44,129.78 139.02,129.2 139.02,125.62 138.85,125.44 136.64,125.44 136.5,125.3 134.43,125.3 134.38,125.36 134.38,126.47 134.44,126.53 135.06,126.53 135.28,126.75 135.28,128.4 135.39,128.51 135.8,128.51 135.94,128.66 135.94,130.56 136.33,130.95 138.16,130.95
N123984271 on TOP (solid shape): 135.26,122.75 135.26,119.37 136.28,118.35 136.28,118.1 136.15,117.97 132.22,117.97 131.84,118.35 131.84,120.77 131.86,120.79 131.86,122.57 132.47,123.18 134.83,123.18
N123984271 on BOTTOM (solid shape): 135.09,123.15 136.26,123.15 136.5,122.91 136.5,120.65 136.92,120.23 136.92,117.97 136.53,117.59 134.53,117.59 134.53,119.75 133.72,119.75 133.72,117.62 133.69,117.59 131.71,117.59 131.33,117.97 131.33,122.8 131.58,123.05 132.55,123.05 132.73,123.24 135,123.24
N123984459 on TOP (solid shape): 97.04,123.05 97.04,120.26 96.91,120.13 95.89,120.13 95.77,120.26 95.77,123.05 95.89,123.18 96.91,123.18
N123984461 on TOP (solid shape): 94.37,122.55 94.37,120.26 94.24,120.13 93.35,120.13 93.23,120.26 93.23,122.55 93.35,122.67 94.24,122.67
N123984461 on BOTTOM (solid shape): 92.51,125.88 92.51,124.72 92.72,124.51 96.39,124.51 96.53,124.37 96.53,120.39 95.96,119.81 88.96,119.81 88.78,119.99 88.78,121.4 88.79,121.41 88.79,121.53 88.78,121.56 88.78,123.18 90.38,124.78 90.43,124.78 91.63,125.97 92.42,125.97
N128803011 on BOTTOM (solid shape): 100.82,10.68 100.8,10.66 99.04,10.66 98.66,10.28 97.04,10.28 95.77,9.01 94.12,9.01 93.86,9.26 93.86,10.91 94.12,11.17 100.82,11.17
N128828208 on TOP (solid shape): 117.23,123.05 117.23,120.39 117.1,120.26 116.09,120.26 115.96,120.39 115.96,123.05 116.09,123.18 117.1,123.18
N128828374 on TOP (solid shape): 107.32,123.05 107.32,120.26 107.2,120.13 106.31,120.13 106.18,120.26 106.18,123.05 106.31,123.18 107.2,123.18
N128835022 on TOP (solid shape): 80.15,116.83 80.15,114.93 80.02,114.8 79,114.8 78.11,115.69 78.11,117.85 78.24,117.97 79,117.97
N128835130 on TOP (solid shape): 136.53,122.24 136.53,119.5 136.47,119.43 135.58,119.43 135.46,119.56 135.46,122.23 135.58,122.35 136.42,122.35
N128884096 on TOP (solid shape): 25.42,39.21 25.42,36.09 25.15,35.83 25.15,34.79 24.62,34.25 23.68,34.25 23.2,33.77 21.9,33.77 21.55,34.13 20.1,34.13 19.6,33.63 18.39,33.63 18.27,33.75 18.27,34.69 18.35,34.76 21.95,34.76 21.98,34.73 22.28,34.73 22.74,35.19 24.11,35.19 24.27,35.35 24.27,35.98 24.7,36.41 24.7,39.24 24.77,39.3 25.32,39.3
N128884096 on BOTTOM (solid shape): 23.12,34.79 23.12,33.77 22.92,33.57 21.94,33.57 21.77,33.74 21.77,34.7 21.99,34.92 22.99,34.92
N128884110 on TOP (solid shape): 21.53,33.69 21.53,32.39 21.48,32.34 20.93,32.34 20.32,31.74 19.99,31.74 19.88,31.85 19.88,33.46 20.2,33.78 21.45,33.78
N128884110 on TOP (solid shape): 22.34,37.4 22.34,37.18 21.99,36.83 21.99,36.82 21.85,36.68 21.85,35.25 21.6,34.99 18.39,34.99 18.27,35.11 18.27,35.34 18.37,35.44 18.37,36.92 19.01,37.56 22.18,37.56
N128884110 on BOTTOM (solid shape): 24.65,37.61 24.65,36.58 24.55,36.48 23.68,36.48 22.63,35.42 21.93,35.42 21.42,34.92 21.42,33.9 21.16,33.63 21.14,33.63 20.62,33.11 18.5,33.11 17.8,33.82 17.8,35.15 18.11,35.47 18.98,35.47 19.19,35.68 19.19,37.28 19.47,37.56 22.84,37.56 22.86,37.54 22.97,37.54 23.12,37.69 24.57,37.69
N128884118 on BOTTOM (solid shape): 23.46,32.55 23.28,31.95 23.88,32.13 25.54,30.47 25.54,29.8 25.51,29.77 25.06,29.77 25.04,29.75 24.71,29.39 25.04,29.04 25.06,29.01 25.59,29.01 25.59,28.27 25.38,28.06 18.03,28.06 17.81,28.27 17.81,29.49 18.02,29.7 18.02,32.55 18.24,32.77 23.24,32.77
N128885024 on BOTTOM (solid shape): 28.77,35.7 28.77,34.9 28.69,34.81 28.56,34.81 28.03,34.28 28.03,32.6 27.9,32.48 27.54,32.48 26.93,31.87 26.65,31.87 26.55,31.97 26.55,32.13 27.01,32.58 27.01,32.68 27.09,32.76 27.09,34.25 28.57,35.74 28.73,35.74
N129089927 on BOTTOM (solid shape): 261.43,17.09 261.43,16.79 261.26,16.61 260.72,16.61 260.3,16.2 260.3,15.38 260.49,15.19 261.5,15.19 262.15,15.84 262.15,16.61 262.23,16.68 262.34,16.68 262.42,16.61 262.42,15.48 262.06,15.13 262.06,14.38 261.84,14.16 260.81,14.16 260.51,13.86 260.51,11.9 260.36,11.75 259.3,11.75 259.24,11.81 259.24,13.6 258.43,14.42 258.43,16.25 258.53,16.35 259.37,16.35 260.18,17.16 261.36,17.16
N129090627 on BOTTOM (solid shape): 265.93,17.15 267.22,17.15 267.47,16.91 268.34,16.91 268.61,16.63 268.61,14.29 265.97,11.65 262.93,11.65 262.85,11.73 262.85,13.86 262.95,13.95 264.85,13.95 265.01,14.11 265.01,15.03 264.66,15.38 264.66,16.61 264.73,16.68 264.86,16.68 264.91,16.63 264.91,15.64 265.46,15.08 266.8,15.08 267.12,15.4 267.12,16.02 266.63,16.5 265.82,16.5 265.62,16.7 265.62,17.08 265.71,17.17 265.91,17.17
N131681151 on TOP (solid shape): 144.71,58.87 144.71,57.44 144.54,57.27 142.5,57.27 142.25,57.52 142.25,58.41 142.76,58.92 144.66,58.92
N131712748 on BOTTOM (solid shape): 173.42,55.03 174.48,55.03 174.53,54.98 174.53,54.88 174.48,54.83 174.29,54.83 174.24,54.89 173.33,54.89 172.96,54.52 171.97,54.52 171.84,54.65 171.84,55.31 171.9,55.37 172.39,55.37 172.4,55.39 173.06,55.39
N131748830 on TOP (solid shape): 193.68,71.36 193.68,70.35 193.81,70.22 194.07,70.22 194.24,70.04 194.24,68.98 194.17,68.9 192.59,68.9 192.41,69.08 192.41,71.49 192.54,71.62 193.43,71.62
N131748958 on TOP (solid shape): 206.03,56.3 206.16,56.3 206.17,56.31 207.01,56.31 207.07,56.25 207.07,55.69 207.02,55.64 205.93,55.64 205.29,55 205.29,54.12 205.26,54.09 205.13,54.09 205.08,54.14 205.08,54.31 205.09,54.32 205.09,56.39 205.21,56.51 205.83,56.51
N131913656 on TOP (solid shape): 204.07,57.72 204.07,57.09 204.03,57.05 201.9,57.05 201.86,57.09 201.86,57.75 204.04,57.75
N132881948 on BOTTOM (solid shape): 133.21,129.5 133.21,128.79 133.36,128.64 133.36,127.9 133.49,127.77 133.49,126.88 133.41,126.8 133.29,126.8 133.21,126.88 133.21,127.6 132.42,128.39 132.42,129.45 132.52,129.56 133.16,129.56
N132883570 on BOTTOM (solid shape): 131.72,126.14 132.47,126.14 132.55,126.06 132.55,125.91 132.49,125.85 130.49,125.85 130.38,125.96 130.38,126.47 130.44,126.53 131.33,126.53
N132883768 on BOTTOM (solid shape): 135.72,130.9 135.72,130.09 135.54,129.91 133.63,129.91 133.5,130.04 133.5,130.92 133.64,131.05 135.57,131.05
N132883846 on BOTTOM (solid shape): 135.75,129.35 135.75,128.74 135.7,128.69 135.32,128.69 135.09,128.46 135.09,127.81 135,127.72 135,126.87 134.91,126.79 134.79,126.79 134.7,126.88 134.7,127.66 134.63,127.73 134.63,128 134.64,128.09 134.63,128.19 134.63,129.28 134.76,129.41 135.69,129.41
N132883854 on BOTTOM (solid shape): 134.5,129.35 134.5,126.86 134.43,126.79 134.28,126.79 134.2,126.86 134.2,127.76 134.03,127.94 134.03,128.36 133.74,128.64 133.59,128.64 133.51,128.72 133.51,129.34 133.58,129.41 134.44,129.41
N133233549 on BOTTOM (solid shape): 18.98,36.86 18.98,35.85 18.81,35.68 17.79,35.68 17.61,35.85 17.61,36.38 17.78,36.55 18.03,36.55 18.51,37.03 18.81,37.03
N134534683 on TOP (solid shape): 30.7,41.4 30.7,40.85 30.43,40.58 28.05,40.58 27.95,40.69 27.95,41.47 28.08,41.6 29.09,41.6 29.12,41.63 30.47,41.63

Small or netless copper shapes (teardrops, artwork), in the pictures only: 274 on TOP, 32 on BOTTOM, 1 on IN1, 1 on VCC, 58 on IN2, 13 on IN3

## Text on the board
Ref Des/Silkscreen Bottom: H20 | H23 | H17 | H1 | H3 | H10 | H4 | H2 | H11 | H5 | H6 | H19 | H12 | H13 | DC | ONLY DDR4 | BL | TP | RTC | HDD
User.Comments: LA-D993P | 2016-11-10 | 2017-11-10 | BBV00/10 | Ken_Yang
Ref Des/Silkscreen Top: H23 | H17 | H1 | H3 | H10 | H4 | H2 | H11 | H19 | H12 | H13 | KB | PWR
IN4: IN4
GND3: GND3
BODY_CENTER: L7 | L8 | L9 | L10 | VCC
User.43: IMPEDANCE
User.45: trace Width | Width/Space | SB_1_2mm-4mil1V1-EM370D-10L WitchOutC_160301 | GND2 | IN4 | 7.3 | 6 | 50 ohm | 3.7 | 4.5 | 5 | 4.6/4.2 | 4.9/3.8 | 80 ohm | 4.5/4.3 | 3.7/3.6 | 85 ohm | 3.7/4.2 | 4.5/5.2 | 88 ohm | 4.5/6 | 3.5/9.6 | 3.5/6 | L2/L4 | L4/L7 | L7/L9 | Ref | L2 | L9 | FIGURE | SIZE | 8.0 | 20.0 | 28.0 | 35.0 | 98.0 | 110.0 | 118.0 | 126.0 | 130.0 | 146.0 | 43.0 | 63.0 | 83.0 | 47.0x24.0 | 51.0x24.0 | 71.0x31.0 | 79.0x31.0 | 93.0x31.0 | 94.0x39.0 | 94.0x83.0 | DRILL CHART: TOP to BOTTOM | ALL UNITS ARE IN MILS | TOLERANCE | +3.0/-3.0 | +2.0/-2.0 | PLATED | NON-PLATED | QTY | 8766 | 19 | 18 | 8 | 3 | 1 | 2 | 4
